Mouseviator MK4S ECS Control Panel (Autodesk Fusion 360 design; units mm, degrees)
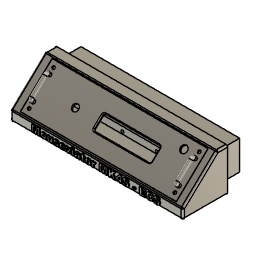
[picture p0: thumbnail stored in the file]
parameter "control_panel_width" = 180
parameter "control_panel_height" = 50 (= "lcd1602_height + ( 2 * panel_wall_thick ) + ( 2 * panel_lcd_gap )")
parameter "lcd1602_height" = 36
parameter "lcd1602_width" = 80
parameter "panel_wall_thick" = 2
parameter "encoder_hole_d" = 7.5
parameter "encoder_board_d" = 24
parameter "speaker_outer_d" = 12
parameter "speaker_hight" = 9
parameter "speaker_inner_d" = 2
parameter "led_mount_hole_d" = 8
parameter "led_distance1" = 20
parameter "led_distance2" = 15
parameter "encoder_distance1" = 20
parameter "lcd1602_display_distance" = 7
parameter "panel_thickness" = 2
parameter "panel_lcd_gap" = 5
parameter "lcd_panel_mount_column_height" = 11 (= "mount_column_width + panel_lcd_gap - 1 mm")
parameter "back_panel_height" = 50
parameter "back_panel_width" = 200
parameter "back_panel_inner_spacing" = 10
parameter "back_panel_inside_cut" = 20
parameter "mount_support_angle" = 136.5
parameter "mount_support_height" = 8
parameter "mount_support_length" = 20
parameter "lock_clearance" = 0.25
parameter "handle_center_to_mount_stand" = 3
parameter "handle_d" = 4
parameter "panel_handle_distance" = 5
parameter "panel_handle_d" = 2.5 (= "panel_handle_distance / 2")
parameter "wago_heigh" = 18
parameter "wago_width" = 6
parameter "wago5_width" = 30 (= "5 * wago_width")
parameter "wago_depth" = 8
parameter "wago10_box_width" = 64 (= "( wago5_width * 2 ) + ( 2 * 2.00 mm )")
parameter "wago_box_height" = 12 (= "wago_depth + ( 2 * 2.00 mm )")
parameter "wago5_box_width" = 34 (= "( wago_width * 5 ) + ( 2 * 2.00 mm )")
parameter "wago3_box_width" = 22.6 (= "wago_width * 3.1 + ( 2 * 2.00 mm )")
parameter "mount_column_width" = 7
parameter "wall_clearance" = 0.5
parameter "wago_wall_thick" = 2
base_feature "Base Feature1"
base_feature "Base Feature1"
base_feature "Base Feature1"
base_feature "Base Feature1"
base_feature "Base Feature1"
base_feature "Base Feature1"
base_feature "Base Feature1"
as_built_joint "As-built1"
sketch "Sketch1" plane through (0, 0, 0) normal (0, 1, 0) x axis (1, 0, 0)
  line L1 (104.8377, -27.8901) -> (-95.1623, -27.8901)
  line L2 (104.8377, 22.1099) -> (104.8377, -27.8901)
  line L3 (-95.1623, 22.1099) -> (104.8377, 22.1099)
  line L4 (-95.1623, -27.8901) -> (-95.1623, 22.1099)
  line L5 (233.5444, -3.1178) -> (-23.8691, -2.6623)
  line L6 (102.8377, -25.8901) -> (-93.1623, -25.8901)
  line L7 (102.8377, 20.1099) -> (102.8377, -25.8901)
  line L8 (-93.1623, 20.1099) -> (102.8377, 20.1099)
  line L9 (-93.1623, -25.8901) -> (-93.1623, 20.1099)
  line L10 (94.8377, -17.8901) -> (-85.1623, -17.8901)
  line L11 (94.8377, 12.1099) -> (94.8377, -17.8901)
  line L12 (-85.1623, 12.1099) -> (94.8377, 12.1099)
  line L13 (-85.1623, -17.8901) -> (-85.1623, 12.1099)
  line L14 (96.8377, -19.8901) -> (-87.1623, -19.8901)
  line L15 (96.8377, 14.1099) -> (96.8377, -19.8901)
  line L16 (-87.1623, 14.1099) -> (96.8377, 14.1099)
  line L17 (-87.1623, -19.8901) -> (-87.1623, 14.1099)
  point P2 (-95.1623, -27.8901)
  point P3 (104.8377, -27.8901)
  point P5 (-95.1623, 22.1099)
  horizontal L1
  vertical L2
  horizontal L3
  vertical L4
  midpoint L2 L5
  dimension "d62" distance P2 P3 = 200 (= "back_panel_width")
  dimension "d63" distance P2 P5 = 50 (= "back_panel_height")
extrude "Extrude1" new body sketch "Sketch1" along normal blind 2 (= "panel_thickness")
extrude "Extrude2" add sketch "Sketch1" profile of L13 L10 L11 L12 L17 L14 L15 L16 along normal blind 22 (= "panel_wall_thick + back_panel_inside_cut")
extrude "Extrude3" add sketch "Sketch1" profile of L5 L13 L10 L11 L12 L17 L14 L15 L16 blind 2 (= "panel_wall_thick") from offset 22 (= "panel_wall_thick + back_panel_inside_cut")
extrude "Extrude4" add sketch "Sketch1" profile of L1 L2 L3 L4 L9 L6 L7 L8 no distance stored
sketch "side panel 1" plane through (-95.1623, 0, 0) normal (-1, 0, 0) x axis (0, -1, 0)
  line L1 (-2, 27.8901) -> (50, 27.8901)
  line L2 (-2, -22.1099) -> (-2, 27.8901)
  line L3 (50, -22.1099) -> (-2, -22.1099)
  line L4 (50, 27.8901) -> (50, -22.1099)
  line L5 (10, 27.8901) -> (-2, 27.8901)
  line L6 (-2, -22.1099) -> (-2, 27.8901)
  line L7 (50, -22.1099) -> (-2, -22.1099)
  line L8 (50, -10.1099) -> (50, -22.1099)
  line L9 (50, -10.1099) -> (10, 27.8901)
  line L10 (48, -10.9686) -> (48, -20.1099)
  line L11 (48, -10.9686) -> (9.2014, 25.8901)
  line L12 (9.2014, 25.8901) -> (0, 25.8901)
  line L13 (0, -20.1099) -> (0, 25.8901)
  line L14 (48, -20.1099) -> (0, -20.1099)
  line L15 (-2, 25.8901) -> (0, 25.8901)
  line L16 (-2, -20.1099) -> (0, -20.1099)
  point P6 (-2, 27.8901)
  point P10 (-2, 27.8901)
  point P9 (-2, -22.1099)
  point P12 (-2, -22.1099)
  point P8 (50, -22.1099)
  point P13 (50, -22.1099)
  point P14 (50, -22.1099)
  point P21 (-2, 25.8901)
  point P22 (-2, -20.1099)
  point P11 (10, 27.8901)
  point P15 (50, -10.1099)
  coincident P6 P10
  perpendicular L2 L5
  coincident P9 P12
  coincident P8 P13
  coincident P8 P14
  perpendicular L7 L8
  coincident L6 P21
  perpendicular L6 L15
  coincident L6 P22
  perpendicular L6 L16
  dimension "back_panel_side_length" distance P10 P11 = 12
  dimension "d79" distance P14 P15 = 12 (= "back_panel_side_length")
extrude "Extrude6" cut sketch "side panel 1" profile of L1 L4 L9 against normal blind 215
extrude "Extrude7" add sketch "side panel 1" profile of L1 L2 L3 L4 L5 L6 L7 L8 L9 L10 L14 L11 L12 L15 L16 no distance stored
work_plane "WorkPlane1" AlongDistance 0
sketch "Sketch1" plane through (0, -18.6705, 19.6531) normal (0, -0.6887, 0.725) x axis (-1, 0, 0)
  line L1 (84.8451, -9.6641) -> (-95.1549, -9.6641)
  line L2 (84.8451, 40.3359) -> (84.8451, -9.6641)
  line L3 (-95.1549, 40.3359) -> (84.8451, 40.3359)
  line L4 (-95.1549, -9.6641) -> (-95.1549, 40.3359)
  line L5 (93.7447, 15.3359) -> (-284.0545, 15.3359)
  line L6 (-5.1549, 65.3359) -> (-5.1549, -84.6641)
  line L7 (19.8451, -2.6641) -> (-60.1549, -2.6641)
  line L8 (19.8451, 33.3359) -> (19.8451, -2.6641)
  line L9 (-60.1549, 33.3359) -> (19.8451, 33.3359)
  line L10 (-60.1549, -2.6641) -> (-60.1549, 33.3359)
  line L11 (82.8451, -7.6641) -> (-93.1549, -7.6641)
  line L12 (82.8451, 38.3359) -> (82.8451, -7.6641)
  line L13 (-93.1549, 38.3359) -> (82.8451, 38.3359)
  line L14 (-93.1549, -7.6641) -> (-93.1549, 38.3359)
  line L15 (-51.4549, 8.5859) -> (10.9451, 8.5859)
  line L16 (11.9451, 9.5859) -> (11.9451, 22.0859)
  line L17 (10.9451, 23.0859) -> (-51.4549, 23.0859)
  line L18 (-52.4549, 22.0859) -> (-52.4549, 9.5859)
  line L19 (12.9451, 9.5859) -> (12.9451, 22.0859)
  line L20 (-51.4549, 7.5859) -> (10.9451, 7.5859)
  line L21 (-53.4549, 22.0859) -> (-53.4549, 9.5859)
  line L22 (10.9451, 24.0859) -> (-51.4549, 24.0859)
  line L23 (-61.1549, 3.3359) -> (-54.1549, 3.3359)
  line L24 (-61.1549, -7.6641) -> (-61.1549, 3.3359)
  line L25 (-54.1549, -7.6641) -> (-54.1549, 3.3359)
  line L26 (-54.1549, -7.6641) -> (-61.1549, -7.6641)
  line L27 (-86.1549, -7.6641) -> (-93.1549, -7.6641)
  line L28 (-86.1549, -0.6641) -> (-86.1549, -7.6641)
  line L29 (-93.1549, -0.6641) -> (-86.1549, -0.6641)
  line L30 (-93.1549, -7.6641) -> (-93.1549, -0.6641)
  line L31 (82.8451, -7.6641) -> (75.8451, -7.6641)
  line L32 (82.8451, -0.6641) -> (82.8451, -7.6641)
  line L33 (75.8451, -0.6641) -> (82.8451, -0.6641)
  line L34 (75.8451, -7.6641) -> (75.8451, -0.6641)
  line L35 (-86.1549, 31.3359) -> (-93.1549, 31.3359)
  line L36 (-86.1549, 38.3359) -> (-86.1549, 31.3359)
  line L37 (-93.1549, 38.3359) -> (-86.1549, 38.3359)
  line L38 (-93.1549, 31.3359) -> (-93.1549, 38.3359)
  line L39 (82.8451, 31.3359) -> (75.8451, 31.3359)
  line L40 (82.8451, 38.3359) -> (82.8451, 31.3359)
  line L41 (75.8451, 38.3359) -> (82.8451, 38.3359)
  line L42 (75.8451, 31.3359) -> (75.8451, 38.3359)
  line L43 (20.8451, -7.6641) -> (13.8451, -7.6641)
  line L44 (13.8451, -7.6641) -> (13.8451, 3.3359)
  line L45 (13.8451, 3.3359) -> (20.8451, 3.3359)
  line L46 (20.8451, -7.6641) -> (20.8451, 3.3359)
  line L47 (-54.1549, 27.3359) -> (-61.1549, 27.3359)
  line L48 (-61.1549, 27.3359) -> (-61.1549, 38.3359)
  line L49 (-61.1549, 38.3359) -> (-54.1549, 38.3359)
  line L50 (-54.1549, 27.3359) -> (-54.1549, 38.3359)
  line L51 (20.8451, 27.3359) -> (13.8451, 27.3359)
  line L52 (13.8451, 27.3359) -> (13.8451, 38.3359)
  line L53 (13.8451, 38.3359) -> (20.8451, 38.3359)
  line L54 (20.8451, 27.3359) -> (20.8451, 38.3359)
  line L55 (-105.1549, 42.9219) -> (95.1623, 42.9219)
  line L56 (-105.1549, -11.9593) -> (-105.1549, 42.9219)
  line L57 (95.1623, -11.9593) -> (-105.1549, -11.9593)
  line L58 (95.1623, 42.9219) -> (95.1623, -11.9593)
  line L59 (79.3451, 34.8359) -> (79.3451, -4.1641)
  line L60 (-89.6549, 34.8359) -> (-89.6549, -4.1641)
  line L61 (85.2201, -10.0391) -> (-95.5299, -10.0391)
  line L62 (85.2201, 40.7109) -> (85.2201, -10.0391)
  line L63 (-95.5299, 40.7109) -> (85.2201, 40.7109)
  line L64 (-95.5299, -10.0391) -> (-95.5299, 40.7109)
  circle C1 centre (39.8451, 15.3359) radius 12
  circle C2 centre (39.8451, 15.3359) radius 3.75
  arc A1 centre (10.9451, 9.5859) radius 1 clockwise from (11.9451, 9.5859) to (10.9451, 8.5859)
  arc A2 centre (10.9451, 22.0859) radius 1 clockwise from (10.9451, 23.0859) to (11.9451, 22.0859)
  arc A3 centre (-51.4549, 22.0859) radius 1 clockwise from (-52.4549, 22.0859) to (-51.4549, 23.0859)
  arc A4 centre (-51.4549, 9.5859) radius 1 clockwise from (-51.4549, 8.5859) to (-52.4549, 9.5859)
  arc A5 centre (10.9451, 9.5859) radius 2 clockwise from (12.9451, 9.5859) to (10.9451, 7.5859)
  arc A6 centre (-51.4549, 9.5859) radius 2 clockwise from (-51.4549, 7.5859) to (-53.4549, 9.5859)
  arc A7 centre (-51.4549, 22.0859) radius 2 clockwise from (-53.4549, 22.0859) to (-51.4549, 24.0859)
  arc A8 centre (10.9451, 22.0859) radius 2 clockwise from (10.9451, 24.0859) to (12.9451, 22.0859)
  circle C3 centre (-75.1549, 0.3359) radius 4
  circle C4 centre (64.8451, 15.3359) radius 6
  circle C5 centre (17.3451, -0.1641) radius 1.25
  circle C6 centre (17.3451, 30.8359) radius 1.25
  circle C7 centre (-57.6549, 30.8359) radius 1.25
  circle C8 centre (-57.6549, -0.1641) radius 1.25
  circle C9 centre (-89.6549, -4.1641) radius 1.7
  circle C10 centre (79.3451, -4.1641) radius 1.7
  circle C11 centre (-89.6549, 34.8359) radius 1.7
  circle C12 centre (79.3451, 34.8359) radius 1.7
  circle C13 centre (79.3451, 2.3359) radius 2
  circle C14 centre (79.3451, 28.3359) radius 2
  circle C15 centre (-89.6549, 2.3359) radius 2
  circle C16 centre (-89.6549, 28.3359) radius 2
  point P11 (19.8451, 33.3359)
  point P16 (19.8451, 33.3359)
  point P13 (-60.1549, -2.6641)
  point P14 (-60.1549, -2.6641)
  point P22 (39.8451, 15.3359)
  point P49 (64.8451, 15.3359)
  point P52 (-61.1549, -7.6641)
  point P74 (79.3451, -4.1641)
  point P93 (79.3451, -4.1641)
  point P76 (79.3451, 34.8359)
  point P94 (79.3451, 34.8359)
  point P73 (-89.6549, -4.1641)
  point P95 (-89.6549, -4.1641)
  point P75 (-89.6549, 34.8359)
  point P96 (-89.6549, 34.8359)
  point P98 (79.3451, 28.3359)
  point P2 (-95.1549, -9.6641)
  point P3 (84.8451, -9.6641)
  point P5 (-95.1549, 40.3359)
  point P48 (-75.1549, 0.3359)
  point P23 (39.8451, 15.3359)
  point P50 (-54.1549, 3.3359)
  point P51 (-61.1549, 3.3359)
  point P18 (-93.1549, -7.6641)
  point P58 (-86.1549, -7.6641)
  point P60 (-93.1549, -0.6641)
  point P97 (79.3451, 2.3359)
  horizontal L1
  vertical L2
  horizontal L3
  vertical L4
  horizontal L5
  midpoint L4 L5
  vertical L6
  midpoint L1 L6
  horizontal L7
  vertical L8
  horizontal L9
  vertical L10
  coincident P11 P16
  coincident P13 P14
  coincident L5 P22
  concentric C1 C2
  coincident L5 P49
  coincident L11 P52
  horizontal L27
  vertical L28
  horizontal L29
  vertical L30
  coincident P74 P93
  coincident P76 P94
  coincident P73 P95
  coincident P75 P96
  coincident L59 P98
  symmetric L6 C13 C15
  symmetric L6 C14 C16
  dimension "d3" distance P2 P3 = 180 (= "control_panel_width")
  dimension "d4" distance P2 P5 = 50 (= "control_panel_height")
  dimension "d8" distance L1 L7 = 7 (= "panel_wall_thick + panel_lcd_gap")
  dimension "d12" diameter C1 = 24 (= "encoder_board_d")
  dimension "d13" distance L8 P22 = 20 (= "encoder_distance1")
  dimension "d14" diameter C2 = 7.5 (= "encoder_hole_d")
  dimension "display_frame_spacing" distance A1 = 1
  dimension "d20" diameter C3 = 8 (= "led_mount_hole_d")
  dimension "d21" distance L10 P48 = 15 (= "led_distance2")
  dimension "d22" distance L4 P48 = 20 (= "led_distance1")
  dimension "led_distance3" distance L1 P48 = 10
  dimension "d29" diameter C4 = 12 (= "speaker_outer_d")
  dimension "speaker_distance" distance P23 P49 = 25
  dimension "d33" distance P50 P51 = 7
  dimension "d39" distance P18 P58 = 7
  dimension "d40" distance P18 P60 = 7
  dimension "M3_d" diameter C9 = 3.4
  dimension "d53" distance L11 P73 = 3.5 (= "mount_column_width / 2")
  dimension "d54" distance L14 P73 = 3.5 (= "mount_column_width / 2")
  dimension "d55" distance P51 P52 = 11 (= "lcd_panel_mount_column_height")
  dimension "d89" distance L6 L56 = 100 (= "back_panel_width / 2")
  dimension "d90" distance L5 L55 = 27.586 (= "( 55.172 / 2 ) * 1 mm")
  dimension "d151" diameter C13 = 4 (= "handle_d")
  dimension "d155" distance L33 P97 = 3 (= "handle_center_to_mount_stand")
  dimension "d156" diameter C14 = 4
  dimension "d157" distance L39 P98 = 3 (= "handle_center_to_mount_stand")
  dimension "d244" = 0.375 (= "wall_clearance * 0.75")
  dimension "d43" R-Pattern2-uDistance = 169 (= "control_panel_width - ( 2 * panel_wall_thick ) - mount_column_width")
  dimension "d44" R-Pattern2-vDistance = 39 (= "control_panel_height - ( 2 * panel_wall_thick ) - mount_column_width")
  dimension "d48" R-Pattern3-uDistance = 169 (= "control_panel_width - ( 2 * panel_wall_thick ) - mount_column_width")
  dimension "d49" R-Pattern3-vDistance = 39 (= "control_panel_height - ( 2 * panel_wall_thick ) - mount_column_width")
  dimension "d58" R-Pattern3-uDistance = 75 (= "lcd1602_width - ( mount_column_width - panel_wall_thick )")
  dimension "d59" R-Pattern3-vDistance = 35 (= "lcd1602_height - ( panel_wall_thick / 2 )")
work_plane "WorkPlane1" AlongDistance 0
sketch "front panel cutout" plane through (0, -18.6705, 19.6531) normal (0, -0.6887, 0.725) x axis (0, -0.725, -0.6887)
  line L1 (40.8359, 95.6549) -> (40.8359, -85.3451)
  line L2 (-10.1641, 95.6549) -> (40.8359, 95.6549)
  line L3 (-10.1641, -85.3451) -> (-10.1641, 95.6549)
  line L4 (40.8359, -85.3451) -> (-10.1641, -85.3451)
extrude "Extrude8" cut sketch "front panel cutout" no distance stored
extrude "Extrude1" new body sketch "Sketch1" profile of L1 L2 L3 L4 L11 L12 L13 L14 C2 L19 A5 L22 A7 L20 A6 L21 A8 C3 C4 L23 L24 L25 L26 C5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 no distance stored bodies "front panel"
extrude "Extrude2" add sketch "Sketch1" profile of L11 L13 L23 L24 L25 L26 C5 C6 C7 C8 L43 L44 L45 L46 L47 L48 L49 L50 L51 L52 L53 L54 against normal blind 9 (magnitude of "-( panel_wall_thick + lcd1602_display_distance )")
sketch "Sketch5" plane through (0, -12.4717, 13.1281) normal (0, 0.6887, -0.725) x axis (-1, 0, 0)
  line L1 (-54.1549, -3.3359) -> (-61.1549, -3.3359)
  line L2 (-54.1549, 7.6641) -> (-54.1549, -3.3359)
  line L3 (-61.1549, 7.6641) -> (-54.1549, 7.6641)
  line L4 (-61.1549, -3.3359) -> (-61.1549, 7.6641)
hole "Hole1" HoleDepth 6.3 (= "lcd1602_display_distance * 0.9") HoleDiameter 2.4 TipAngle 118
sketch "Sketch4" plane through (-95.1623, 0, 0) normal (-1, 0, 0) x axis (0, -1, 0)
  line L1 (-2, -22.1099) -> (-2, 27.8901)
  line L2 (50, -22.1099) -> (-2, -22.1099)
  line L3 (50, -10.1099) -> (50, -22.1099)
  line L4 (10, 27.8901) -> (50, -10.1099)
  line L5 (-2, 27.8901) -> (10, 27.8901)
  line L6 (-2, 27.8901) -> (10, 27.8901)
  line L7 (49.7888, -9.9094) -> (10, 27.8901)
  line L8 (50, -22.1099) -> (50, -10.1099)
  line L9 (50, -22.1099) -> (-2, -22.1099)
  line L10 (0, 25.8901) -> (9.2014, 25.8901)
  line L11 (0, -20.1099) -> (0, 25.8901)
  line L12 (48, -20.1099) -> (0, -20.1099)
  line L13 (48, -10.9686) -> (48, -20.1099)
  line L14 (9.2014, 25.8901) -> (48, -10.9686)
  line L15 (12.0934, 14.9294) -> (18.189, 20.1105)
  line L16 (-24, 19.8901) -> (-2, 19.8901)
  line L17 (-24, -14.1099) -> (-2, -14.1099)
  line L18 (-24, 19.8901) -> (-24, -14.1099)
  line L19 (-22, 17.8901) -> (-2, 17.8901)
  line L20 (-22, 17.8901) -> (-22, -12.1099)
  line L21 (-22, -12.1099) -> (-2, -12.1099)
  line L22 (0, 17.8901) -> (-2, 17.8901)
  line L23 (0, -12.1099) -> (-2, -12.1099)
  line L24 (0, 17.8901) -> (12.0934, 14.9294)
  line L25 (35.879, -7.7295) -> (41.389, -1.9295)
  line L26 (35.879, -22.1099) -> (35.879, -7.7295)
  point P7 (18.189, 20.1105)
  point P22 (18.189, 20.1105)
  point P32 (0, 17.8901)
  point P33 (0, -12.1099)
  point P9 (41.389, -1.9295)
  point P34 (41.389, -1.9295)
  point P36 (35.879, -22.1099)
  point P23 (12.0934, 14.9294)
  point P35 (35.879, -7.7295)
  coincident P7 P22
  coincident L11 P32
  perpendicular L11 L22
  coincident L11 P33
  perpendicular L11 L23
  coincident P9 P34
  perpendicular L14 L25
  coincident L2 P36
  perpendicular L2 L26
  dimension "d105" distance P22 P23 = 8 (= "mount_support_height")
  dimension "d107" distance P34 P35 = 8 (= "mount_support_height")
extrude "Extrude9" add sketch "Sketch4" profile of L14 L10 L11 L12 L13 L15 L24 L25 L26 no distance stored
extrude "Extrude10" add sketch "Sketch4" profile of L14 L10 L11 L12 L13 L15 L24 L25 L26 along normal blind 20 (= "mount_support_length")
hole "Hole2" HoleDepth 6.4 (= "mount_support_height * 0.8") HoleDiameter 3.4 TipAngle 180
sketch "speaker" plane through (0, -18.6705, 19.6531) normal (0, -0.6887, 0.725) x axis (-1, 0, 0)
  line L1 (64.8451, 30) -> (64.8451, 2.9899)
  line L2 (49, 15.3359) -> (77.5103, 15.3359)
  line L3 (69.3451, 21.9503) -> (69.3451, 8.7216)
  line L4 (60.3451, 21.9503) -> (60.3451, 8.7216)
  line L5 (52.7594, 13.3359) -> (76.9307, 13.3359)
  line L6 (52.7594, 17.3359) -> (76.9307, 17.3359)
  line L7 (53.2665, 11.3359) -> (76.4236, 11.3359)
  line L8 (53.2665, 19.3359) -> (76.4236, 19.3359)
  line L9 (70.5842, 17.0859) -> (74.6908, 17.0859)
  line L10 (54.9994, 13.5859) -> (59.106, 13.5859)
  circle C1 centre (64.8451, 15.3359) radius 6
  circle C2 centre (64.8451, 15.3359) radius 8
  circle C3 centre (64.8451, 15.3359) radius 8.25
  circle C4 centre (64.8451, 15.3359) radius 10.25
  circle C5 centre (64.8451, 15.3359) radius 12.25
  circle C6 centre (64.8451, 15.3359) radius 10
  point P8 (69.3451, 8.7216)
  point P9 (69.3451, 21.9503)
  point P10 (60.3451, 8.7216)
  point P11 (60.3451, 21.9503)
  point P15 (76.9307, 13.3359)
  point P16 (52.7594, 13.3359)
  point P17 (76.9307, 17.3359)
  point P18 (52.7594, 17.3359)
  point P19 (76.4236, 11.3359)
  point P20 (53.2665, 11.3359)
  point P21 (76.4236, 19.3359)
  point P22 (53.2665, 19.3359)
  point P24 (74.6908, 17.0859)
  point P25 (70.5842, 17.0859)
  point P26 (59.106, 13.5859)
  point P27 (54.9994, 13.5859)
  vertical L1
  perpendicular L1 L2
  vertical L3
  coincident C2 P8
  coincident C2 P9
  symmetric L1 P8 P10
  symmetric L1 P9 P11
  horizontal L5
  coincident C5 P15
  coincident C5 P16
  symmetric L2 P15 P17
  symmetric L2 P16 P18
  horizontal L7
  coincident C5 P19
  coincident C5 P20
  symmetric L2 P19 P21
  symmetric L2 P20 P22
  coincident C6 P24
  coincident C1 P25
  coincident C1 P26
  coincident C6 P27
  dimension "d124" = 2 (= "panel_wall_thick")
  dimension "d125" distance L1 L3 = 4.5
  dimension "d127" = 2.25 (= "panel_wall_thick + lock_clearance")
  dimension "d128" = 4.25 (= "2 * panel_wall_thick + lock_clearance")
  dimension "d129" = 6.25 (= "3 * panel_wall_thick + lock_clearance")
  dimension "d130" distance L2 L5 = 2 (= "panel_wall_thick")
  dimension "d131" distance L2 L7 = 4 (= "2 * panel_wall_thick")
  dimension "d138" = 4 (= "2 * panel_thickness")
extrude "Extrude3" add sketch "speaker" profile of C3 C4 C5 L5 L6 L7 L8 no distance stored
extrude "Extrude4" add sketch "speaker" profile of C3 C4 C5 L5 L6 L7 L8 no distance stored from offset -4.25 (= "-( ( 2 * panel_wall_thick ) + lock_clearance )")
extrude "Extrude5" new body sketch "speaker" profile of C1 C2 L3 L4 L5 L6 L7 L8 L9 L10 no distance stored bodies "speaker holder"
extrude "Extrude6" add sketch "speaker" profile of C1 C2 L3 L4 C3 L5 L6 L7 L8 C6 L9 L10 no distance stored
extrude "Extrude7" add sketch "speaker" profile of C1 C2 L3 L4 L5 L6 L7 L8 L9 L10 no distance stored
hole "Hole3" HoleDepth 2 (= "panel_wall_thick") HoleDiameter 2.2 TipAngle 180
fillet "Fillet1" radius 1 (= "panel_wall_thick / 2")
sketch "handle side" plane through (-95.1623, 0, 0) normal (-1, 0, 0) x axis (0, -1, 0)
  line L1 (40.8453, 5.4836) -> (25.6203, 19.9474)
  line L2 (22.0859, 19.8567) -> (20.364, 18.0442)
  line L3 (40.9359, 1.9492) -> (39.214, 0.1367)
  arc A1 centre (23.8984, 18.1349) radius 2.5 clockwise from (22.0859, 19.8567) to (25.6203, 19.9474)
  arc A2 centre (39.1234, 3.6711) radius 2.5 clockwise from (40.8453, 5.4836) to (40.9359, 1.9492)
  point P2 (20.364, 18.0442)
  point P4 (20.364, 18.0442)
  point P3 (39.214, 0.1367)
  point P5 (39.214, 0.1367)
  coincident P2 P4
  coincident P3 P5
  tangent L1 A1
  tangent L2 A1
  tangent L1 A2
  tangent L3 A2
  equal A1 A2
  dimension "d166" radius A1 = 2.5 (= "panel_handle_d")
pipe "Pipe1" SectionSize 4 (= "handle_d") SectionThickness 1 bodies "handle1"
sketch "Sketch10" plane through (0, -18.6705, 19.6531) normal (0, 0.6887, -0.725) x axis (-1, 0, 0)
  circle C1 centre (95.1623, -2.3359) radius 2
hole "Hole4" HoleDepth 3.5 (= "panel_handle_distance * 0.7") HoleDiameter 2.2 TipAngle 180
move "Move1"
copy_paste_bodies "CopyPasteBodies1"
move "Move2"
fillet "Fillet1" radius 2 (= "panel_wall_thick") 2 (= "panel_wall_thick")
position "Position1"
sketch "Sketch5" plane through (0, 0, 0) normal (0, 1, 0) x axis (1, 0, 0)
  line L1 (-95.1623, 22.1099) -> (104.8377, 22.1099)
  line L2 (-95.1623, -27.8901) -> (-95.1623, 22.1099)
  line L3 (104.8377, -27.8901) -> (-95.1623, -27.8901)
  line L4 (104.8377, 22.1099) -> (104.8377, -27.8901)
  line L5 (113.629, -22.8901) -> (-106.4322, -22.8901)
  line L6 (233.5444, -3.1178) -> (-23.8691, -2.6623)
  circle C1 centre (-55.1623, -22.8901) radius 1.7
  circle C2 centre (64.8377, -22.8901) radius 1.7
  circle C3 centre (-15.1623, -22.8901) radius 1.7
  circle C4 centre (24.8377, -22.8901) radius 1.7
  circle C5 centre (-55.0905, 17.6761) radius 1.7
  circle C6 centre (-15.0908, 17.5345) radius 1.7
  circle C7 centre (24.909, 17.3929) radius 1.7
  circle C8 centre (64.9087, 17.2514) radius 1.7
  point P10 (-55.1623, -22.8901)
  point P11 (64.8377, -22.8901)
  point P12 (-15.1623, -22.8901)
  point P13 (24.8377, -22.8901)
  perpendicular L4 L5
  coincident L5 P10
  coincident L5 P11
  coincident L5 P12
  coincident L5 P13
  symmetric L6 C1 C5
  symmetric L6 C2 C8
  symmetric L6 C3 C6
  symmetric L6 C4 C7
  dimension "d178" distance L3 L5 = 5 (= "back_panel_inner_spacing / 2")
  dimension "d179" diameter C1 = 3.4 (= "M3_d")
  dimension "bp_mount_hole_spacing" distance L2 P10 = 40 (= "back_panel_width / 5")
  dimension "d181" diameter C2 = 3.4 (= "M3_d")
  dimension "d182" distance L4 P11 = 40 (= "bp_mount_hole_spacing")
  dimension "d183" diameter C3 = 3.4 (= "M3_d")
  dimension "d184" diameter C4 = 3.4 (= "M3_d")
  dimension "d185" distance P10 P12 = 40 (= "bp_mount_hole_spacing")
  dimension "d186" distance P11 P13 = 40 (= "bp_mount_hole_spacing")
hole "Hole2" HoleDepth 3.5 HoleDiameter 3.4 TipAngle 180
sketch "Sketch6" plane through (0, 22, 0) normal (0, -1, 0) x axis (1, 0, 0)
  line L1 (-85.1623, 17.8901) -> (94.8377, 17.8901)
  line L2 (-85.1623, -12.1099) -> (-85.1623, 17.8901)
  line L3 (94.8377, -12.1099) -> (-85.1623, -12.1099)
  line L4 (94.8377, 17.8901) -> (94.8377, -12.1099)
  line L5 (96.8377, 19.8901) -> (-89.9133, 19.8901)
  line L6 (-89.9133, 19.8901) -> (-89.9133, -14.1099)
  line L7 (-89.9133, -14.1099) -> (96.8377, -14.1099)
  line L8 (96.8377, -14.1099) -> (96.8377, 19.8901)
  line L9 (10.283, 2.8901) -> (-190.1096, 2.8901)
  line L10 (94.8377, 17.8901) -> (-87.9133, 17.8901)
  line L11 (94.8377, -12.1099) -> (94.8377, 17.8901)
  line L12 (-87.9133, -12.1099) -> (94.8377, -12.1099)
  line L13 (-87.9133, 17.8901) -> (-87.9133, -12.1099)
  line L14 (4.0867, 2.8901) -> (-29.9133, 2.8901)
  line L15 (4.0867, 14.8901) -> (4.0867, 2.8901)
  line L16 (-29.9133, 14.8901) -> (4.0867, 14.8901)
  line L17 (-29.9133, 2.8901) -> (-29.9133, 14.8901)
  line L18 (26.6867, 14.8901) -> (4.0867, 14.8901)
  line L19 (26.6867, 2.8901) -> (26.6867, 14.8901)
  line L20 (4.0867, 2.8901) -> (26.6867, 2.8901)
  line L21 (4.0867, 14.8901) -> (4.0867, 2.8901)
  line L22 (24.6867, 12.8901) -> (6.0867, 12.8901)
  line L23 (24.6867, 4.8901) -> (24.6867, 12.8901)
  line L24 (6.0867, 4.8901) -> (24.6867, 4.8901)
  line L25 (6.0867, 12.8901) -> (6.0867, 4.8901)
  line L26 (-27.9133, 12.8901) -> (2.0867, 12.8901)
  line L27 (-27.9133, 4.8901) -> (-27.9133, 12.8901)
  line L28 (2.0867, 4.8901) -> (-27.9133, 4.8901)
  line L29 (2.0867, 12.8901) -> (2.0867, 4.8901)
  line L30 (-29.9133, -9.1099) -> (4.0867, -9.1099)
  line L31 (-29.9133, 2.8901) -> (-29.9133, -9.1099)
  line L32 (4.0867, 2.8901) -> (-29.9133, 2.8901)
  line L33 (4.0867, -9.1099) -> (4.0867, 2.8901)
  line L34 (2.0867, 0.8901) -> (-27.9133, 0.8901)
  line L35 (2.0867, -7.1099) -> (2.0867, 0.8901)
  line L36 (-27.9133, 0.8901) -> (-27.9133, -7.1099)
  line L37 (-27.9133, -7.1099) -> (2.0867, -7.1099)
  line L38 (6.0867, 0.8901) -> (24.6867, 0.8901)
  line L39 (6.0867, -7.1099) -> (6.0867, 0.8901)
  line L40 (24.6867, 0.8901) -> (24.6867, -7.1099)
  line L41 (24.6867, -7.1099) -> (6.0867, -7.1099)
  line L42 (26.6867, 2.8901) -> (26.6867, -9.1099)
  line L43 (4.0867, 2.8901) -> (26.6867, 2.8901)
  line L44 (4.0867, -9.1099) -> (4.0867, 2.8901)
  line L45 (26.6867, -9.1099) -> (4.0867, -9.1099)
  circle C1 centre (-69.9133, 2.8901) radius 5.375
  point P10 (-69.9133, 2.8901)
  point P17 (-29.9133, 2.8901)
  point P34 (-29.9133, 2.8901)
  point P18 (4.0867, 2.8901)
  point P35 (4.0867, 2.8901)
  point P19 (4.0867, 14.8901)
  point P32 (4.0867, -9.1099)
  point P20 (-29.9133, 14.8901)
  point P33 (-29.9133, -9.1099)
  point P21 (26.6867, 14.8901)
  point P44 (26.6867, -9.1099)
  point P22 (26.6867, 2.8901)
  point P45 (26.6867, 2.8901)
  point P23 (4.0867, 2.8901)
  point P46 (4.0867, 2.8901)
  point P24 (6.0867, 12.8901)
  point P42 (6.0867, -7.1099)
  point P25 (24.6867, 12.8901)
  point P43 (24.6867, -7.1099)
  point P26 (24.6867, 4.8901)
  point P40 (24.6867, 0.8901)
  point P27 (6.0867, 4.8901)
  point P41 (6.0867, 0.8901)
  point P28 (2.0867, 12.8901)
  point P38 (2.0867, -7.1099)
  point P29 (-27.9133, 12.8901)
  point P39 (-27.9133, -7.1099)
  point P30 (-27.9133, 4.8901)
  point P36 (-27.9133, 0.8901)
  point P31 (2.0867, 4.8901)
  point P37 (2.0867, 0.8901)
  perpendicular L8 L9
  midpoint L6 L9
  coincident P10 L9
  horizontal L14
  vertical L15
  horizontal L16
  vertical L17
  coincident L9 P17
  horizontal L18
  vertical L19
  horizontal L20
  vertical L21
  symmetric L9 P17 P34
  symmetric L9 P18 P35
  symmetric L9 P19 P32
  symmetric L9 P20 P33
  symmetric L9 P21 P44
  symmetric L9 P22 P45
  symmetric L9 P23 P46
  symmetric L9 P24 P42
  symmetric L9 P25 P43
  symmetric L9 P26 P40
  symmetric L9 P27 P41
  symmetric L9 P28 P38
  symmetric L9 P29 P39
  symmetric L9 P30 P36
  symmetric L9 P31 P37
  dimension "back_panel_cable_hole_d" diameter C1 = 10.75
  dimension "d192" distance L6 P10 = 20 (= "bp_mount_hole_spacing / 2")
  dimension "d216" = 2 (= "panel_wall_thick")
  dimension "d232" distance P17 P18 = 34 (= "wago5_box_width")
  dimension "d233" distance P17 P20 = 12 (= "wago_box_height")
  dimension "d234" distance P10 L17 = 40 (= "bp_mount_hole_spacing")
  dimension "d235" distance P19 P21 = 22.6 (= "wago3_box_width")
  dimension "d236" distance P19 P23 = 12 (= "wago_box_height")
  dimension "d237" = 2 (= "wago_wall_thick")
extrude "Extrude11" cut sketch "Sketch6" profile of C1 L9 no distance stored
extrude "Extrude12" add sketch "Sketch6" profile of L9 L14 L15 L16 L17 L18 L19 L20 L21 L22 L24 L23 L25 L26 L27 L28 L29 L30 L31 L32 L33 L34 L35 L36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 along normal blind 12 (= "wago_box_height")
sketch "Sketch7" plane through (0, -50, 0) normal (0, -1, 0) x axis (1, 0, 0)
  dimension "d239" = 8
emboss "Emboss1" sketch "Sketch7" Depth 1 named "emboss_depth" Horizontal Distance 0 Vertical Distance 0 Rotation Angle 0
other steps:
base_feature "Base Feature1" bodies "handle1", "handle1 (1)"
hole "Hole1" HoleDepth 6.4 (= "mount_support_height * 0.8") HoleDiameter 3.4 TipAngle 180
create_component "CreateComponent1"
create_component "CreateComponent2"
create_component "CreateComponent3"
create_component "CreateComponent4"
create_component "CreateComponent5"
create_component "CreateComponent6"
create_component "CreateComponent7"
create_component "CreateComponent1"
create_component "CreateComponent2"
create_component "CreateComponent3"
named bodies: "front panel", "speaker holder", "handle1", "handle1 (1)"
